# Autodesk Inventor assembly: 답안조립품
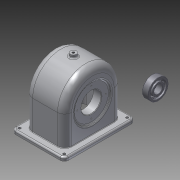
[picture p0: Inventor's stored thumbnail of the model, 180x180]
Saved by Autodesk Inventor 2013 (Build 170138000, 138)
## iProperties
Created: 2016-01
Part Number: 답안조립품
Document SubType Name: Assembly
Designer: Administrator
Author: Administrator
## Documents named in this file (3)
- C:\Documents and Settings\Administrator\바탕 화면\460106v1002\답안조립품.iam
- C:\Documents and Settings\Administrator\바탕 화면\460106v1002\1-본체.ipt
- C:\Documents and Settings\Administrator\바탕 화면\460106v1002\베어링 6203.ipt
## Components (1 placed, 1 different names)
1. 1-본체:1
